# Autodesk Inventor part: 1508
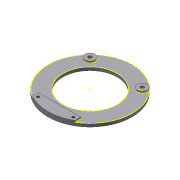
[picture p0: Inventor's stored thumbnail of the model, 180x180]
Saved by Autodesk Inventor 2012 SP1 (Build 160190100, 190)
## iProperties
Created: 2012-02
Part Number: 1508
Material: Aluminum-6061
Document SubType Name: Modeling
Designer: LACO
Density: 2.71 g/cm^3
Mass: 264.183 g
Surface Area: 359.084 cm^2
Volume: 97.4846 cm^3
Author: LACO
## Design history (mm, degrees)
sketch "Sketch1"
  geometry: C1 r 78.74 at (0, 0); A1 r 50.8 centre (0, 0) between (-41.102, 29.854) and (-41.102, -29.854); 3 further points
  constraints: 4 point on circle, 2 centre point, 2 coincident
  dimensions: "d25" = 157.48 diameter of C1; "d26" = 101.6 diameter of A1
extrude "Extrusion1" new body sketch "Sketch1" stored distance "d1" = 6.35; taper "d2" = 0 deg
sketch "Sketch8"
  geometry: L1 (0, 0)-(0, 77.225); L2 (-39.687, -68.007)-(-39.688, -57.15); L3 (-39.688, -57.15)-(39.688, -57.15); L4 (39.687, -68.007)-(39.688, -57.15); A1 r 78.74 centre (0, 0) between (39.687, -68.007) and (-39.687, -68.007) reference; 1 further point
  constraints: 8 end point, 3 point on circle, 2 parallel, 1 coincident, 1 perpendicular, 1 vertical, 1 other
  dimensions: "d64" = 79.375 distance between parallel lines of L4 L2; "d81" = 57.15 distance from line of L3 L1.start
extrude "Extrusion5" join sketch "Sketch8" distance "d66" = 2.54; taper "d67" = 0 deg
sketch "Sketch7"
  geometry: L1 (0, 0)-(0, -38.1); L2 (-39.688, -57.15)-(39.688, -57.15) reference; A1 r 78.74 centre (0, 0) between (-62.145, -48.352) and (62.145, -48.352); A2 r 78.74 centre (0, 0) between (-39.687, -68.007) and (37.465, -69.256) reference; 7 further points; 3 other entities
  constraints: 2 end point, 2 point on circle, 1 centre point, 1 vertical, 1 vertical alignment, 11 other
  dimensions: "d70" = 6.604 dimension on point (33.083, -64.262); "d71" = 7.112 distance from line of L2 point (33.083, -64.262); "d82" = 6.604 dimension on point (-33.084, -64.262); "d83" = 7.112 distance from line of point (-33.084, -64.262) L2
hole "Hole4" sketch "Sketch7" at (-33.084, -64.262), (33.083, -64.262) diameter "d57" = 4.9784; stored, may be unused: countersink angle "d61" = 82 deg, drill point angle "d63" = 118 deg; dims "d58" = 19.05, "d59" = 9.525, "d60" = 6.35, "d62" = 25.4
sketch "Sketch6"
  geometry: L1 (0, 0)-(48.942, -48.942); L2 (0, 0)-(-48.942, -48.942); L3 (0, 0)-(69.215, 0); L4 (0, 0)-(69.215, 0); C1 r 38.1 at (0, 0); C2 r 50.8 at (0, 0) reference; A1 r 69.215 centre (0, 0) between (48.942, -48.942) and (-48.942, -48.942); 2 further points
  constraints: 8 end point, 6 point on circle, 2 centre point, 2 coincident, 2 point on line, 1 horizontal
  dimensions: "d92" = 138.43 diameter of A1; "d93" = 45 deg angle of L1 L3; "d94" = 45 deg angle of L2 L3
hole "Hole3" sketch "Sketch6" at (-48.942, -48.942), (48.942, -48.942) diameter "d46" = 6.7564; stored, may be unused: countersink angle "d50" = 82 deg, drill point angle "d52" = 118 deg; dims "d47" = 19.05, "d48" = 15.24, "d49" = 4.191, "d51" = 25.4
sketch "Sketch10"
  geometry: L1 (-39.688, -57.15)-(39.688, -57.15) reference; L2 (-39.762, 46.402)-(39.762, 46.402); L3 (46.402, 39.762)-(46.402, -57.15); L4 (46.402, -57.15)-(-46.402, -57.15); L5 (-46.402, 39.762)-(-46.402, -57.15); L6 (-39.688, -57.15)-(39.688, -57.15) reference; C1 r 3.378 at (48.942, 48.942) reference; C2 r 3.378 at (-48.942, 48.942) reference; C3 r 50.8 at (0, 0) reference; A1 r 78.74 centre (0, 0) between (39.687, -68.007) and (-39.687, -68.007) reference; A2 r 9.525 centre (-48.942, 48.942) between (-39.762, 46.402) and (-46.402, 39.762); A3 r 9.525 centre (48.942, 48.942) between (39.762, 46.402) and (46.402, 39.762)
  constraints: 8 end point, 4 point on circle, 2 centre point, 2 coincident, 2 perpendicular, 2 tangent, 1 collinear, 1 parallel, 1 vertical
  dimensions: "d85" = 2.54 distance from line of L5 C2.centre; "d90" = 2.54 distance from line of L3 C1.centre; "d91" = 2.54 distance from line of L2 C2.centre
extrude "Extrusion7" cut sketch "Sketch10" stored distance "d88" = 2.54; taper "d89" = 0 deg
sketch "Sketch11"
  geometry: C1 r 3.378 at (48.942, 48.942) reference; C2 r 3.378 at (-48.942, 48.942) reference; C3 r 9.525 at (48.942, 48.942); C4 r 9.525 at (-48.942, 48.942); A1 r 78.74 centre (0, 0) between (39.687, -68.007) and (-39.687, -68.007) reference
  constraints: 2 centre point, 2 coincident, 1 equal radius, 1 tangent
extrude "Extrusion8" join sketch "Sketch11" distance "d96" = 2.54; taper "d97" = 0 deg
sketch "Sketch12"
  geometry: L1 (39.688, -57.15)-(39.687, -68.007) reference; L2 (-39.687, -68.007)-(-39.688, -57.15) reference; L3 (-39.688, -57.15)-(39.688, -57.15) reference; C1 r 50.8 at (0, 0) reference; A1 r 78.74 centre (0, 0) between (39.687, -68.007) and (55.678, 55.678) reference; A2 r 78.74 centre (0, 0) between (55.678, 55.678) and (-55.678, 55.678) reference; A3 r 78.74 centre (0, 0) between (-55.678, 55.678) and (-39.687, -68.007) reference; 2 further points
  constraints: 2 other
body "Solid1"
